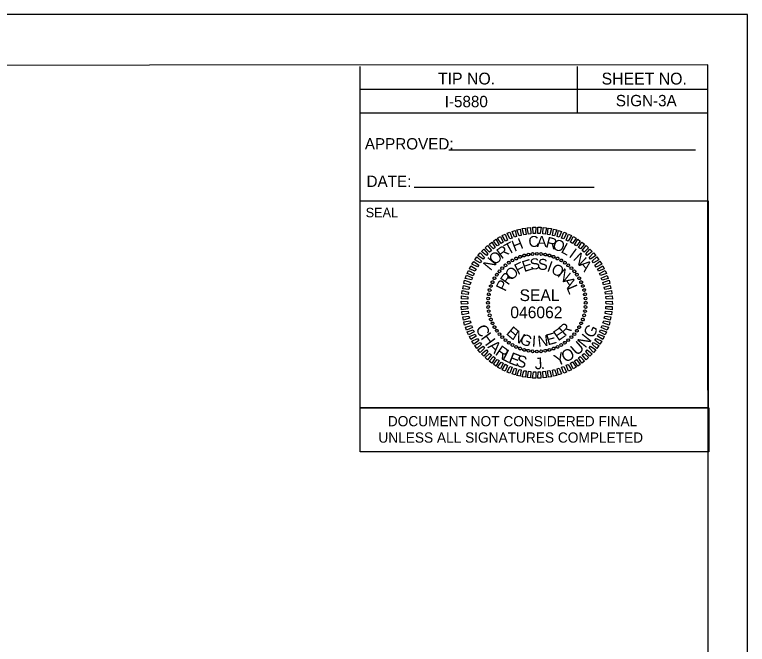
# Model space of a CAD drawing. Extents: x 1727387 to 1728895, y 539219 to 540208.
# Drawn here: x 1727645.2 to 1727723.8, y 539521.4 to 539589 of the extents above; entities that cross this region are included whole.
import ezdxf

# ---------------------------------------------------------------- set-up
doc = ezdxf.new("R2010")
doc.units = 0
for name, color, linetype in [('Default', 7, 'Continuous'), ('Old_Level_2', 7, 'Continuous'), ('Overhead Sheet Border', 7, 'Continuous'), ('Overhead Sheet Text', 7, 'Continuous'), ('Sheet Plot Border Outside CELL', 7, 'Continuous'), ('Sheet Sticker Exception Certification CELL', 7, 'Continuous')]:
    doc.layers.add(name, color=color, linetype=linetype)

msp = doc.modelspace()

# ---------------------------------------------------------------- linework, layer by layer
at = {"layer": 'Old_Level_2'}
for p, q in [((1727700.313, 539563.242), (1727700.313, 539563.242)), ((1727700.762, 539563.312), (1727700.762, 539563.312)), ((1727701.222, 539563.331), (1727701.222, 539563.331)), ((1727701.682, 539563.307), (1727701.682, 539563.307)), ((1727702.133, 539563.242), (1727702.133, 539563.242)), ((1727698.205, 539562.379), (1727698.205, 539562.379)), ((1727698.598, 539562.626), (1727698.598, 539562.626)), ((1727699.002, 539562.842), (1727699.002, 539562.842)), ((1727699.418, 539563.017), (1727699.418, 539563.017)), ((1727699.855, 539563.15), (1727699.855, 539563.15)), ((1727702.574, 539563.156), (1727702.574, 539563.156)), ((1727703.016, 539563.017), (1727703.016, 539563.017)), ((1727703.437, 539562.836), (1727703.437, 539562.836)), ((1727703.848, 539562.634), (1727703.848, 539562.634)), ((1727704.229, 539562.379), (1727704.229, 539562.379)), ((1727697.504, 539561.791), (1727697.504, 539561.791)), ((1727697.844, 539562.111), (1727697.844, 539562.111)), ((1727704.6, 539562.103), (1727704.6, 539562.103)), ((1727704.93, 539561.795), (1727704.93, 539561.795)), ((1727696.92, 539561.091), (1727696.92, 539561.091)), ((1727697.196, 539561.462), (1727697.196, 539561.462)), ((1727705.25, 539561.456), (1727705.25, 539561.456)), ((1727705.517, 539561.094), (1727705.517, 539561.094)), ((1727696.464, 539560.298), (1727696.464, 539560.298)), ((1727696.666, 539560.71), (1727696.666, 539560.71)), ((1727705.765, 539560.701), (1727705.765, 539560.701)), ((1727705.981, 539560.297), (1727705.981, 539560.297)), ((1727696.144, 539559.435), (1727696.144, 539559.435)), ((1727696.283, 539559.877), (1727696.283, 539559.877)), ((1727706.156, 539559.882), (1727706.156, 539559.882)), ((1727706.289, 539559.445), (1727706.289, 539559.445)), ((1727695.992, 539558.544), (1727695.992, 539558.544)), ((1727696.057, 539558.994), (1727696.057, 539558.994)), ((1727706.38, 539558.986), (1727706.38, 539558.986)), ((1727706.451, 539558.538), (1727706.451, 539558.538)), ((1727695.969, 539558.083), (1727695.969, 539558.083)), ((1727701.219, 539558.08), (1727701.219, 539558.08)), ((1727706.469, 539558.078), (1727706.469, 539558.078)), ((1727695.987, 539557.623), (1727695.987, 539557.623)), ((1727696.058, 539557.175), (1727696.058, 539557.175)), ((1727706.381, 539557.166), (1727706.381, 539557.166)), ((1727706.446, 539557.617), (1727706.446, 539557.617)), ((1727696.15, 539556.716), (1727696.15, 539556.716)), ((1727696.283, 539556.279), (1727696.283, 539556.279)), ((1727706.156, 539556.284), (1727706.156, 539556.284)), ((1727706.294, 539556.726), (1727706.294, 539556.726)), ((1727696.457, 539555.864), (1727696.457, 539555.864)), ((1727696.673, 539555.46), (1727696.673, 539555.46)), ((1727705.773, 539555.451), (1727705.773, 539555.451)), ((1727705.975, 539555.863), (1727705.975, 539555.863)), ((1727696.921, 539555.067), (1727696.921, 539555.067)), ((1727697.189, 539554.705), (1727697.189, 539554.705)), ((1727705.242, 539554.699), (1727705.242, 539554.699)), ((1727705.518, 539555.07), (1727705.518, 539555.07)), ((1727697.508, 539554.366), (1727697.508, 539554.366)), ((1727697.838, 539554.058), (1727697.838, 539554.058)), ((1727698.209, 539553.782), (1727698.209, 539553.782)), ((1727704.233, 539553.782), (1727704.233, 539553.782)), ((1727704.594, 539554.05), (1727704.594, 539554.05)), ((1727704.934, 539554.37), (1727704.934, 539554.37)), ((1727698.59, 539553.527), (1727698.59, 539553.527)), ((1727699.001, 539553.325), (1727699.001, 539553.325)), ((1727699.423, 539553.144), (1727699.423, 539553.144)), ((1727699.864, 539553.005), (1727699.864, 539553.005)), ((1727702.584, 539553.011), (1727702.584, 539553.011)), ((1727703.021, 539553.144), (1727703.021, 539553.144)), ((1727703.436, 539553.319), (1727703.436, 539553.319)), ((1727703.84, 539553.535), (1727703.84, 539553.535)), ((1727700.305, 539552.919), (1727700.305, 539552.919)), ((1727700.756, 539552.853), (1727700.756, 539552.853)), ((1727701.217, 539552.83), (1727701.217, 539552.83)), ((1727701.677, 539552.849), (1727701.677, 539552.849)), ((1727702.125, 539552.919), (1727702.125, 539552.919))]:
    msp.add_line(p, q, dxfattribs=at)
for points in [[(1727698.307, 539564.932), (1727698.025, 539565.534), (1727698.336, 539565.665), (1727698.567, 539565)], [(1727698.816, 539565.109), (1727698.565, 539565.732), (1727698.887, 539565.832), (1727699.035, 539565.186)], [(1727699.316, 539565.253), (1727699.085, 539565.908), (1727699.439, 539565.988), (1727699.535, 539565.309)], [(1727699.816, 539565.377), (1727699.637, 539566.043), (1727699.981, 539566.081), (1727700.066, 539565.413)], [(1727700.317, 539565.449), (1727700.19, 539566.116), (1727700.545, 539566.164), (1727700.567, 539565.484)], [(1727700.838, 539565.51), (1727700.774, 539566.189), (1727701.12, 539566.184), (1727701.09, 539565.504)], [(1727701.34, 539565.508), (1727701.329, 539566.188), (1727701.674, 539566.183), (1727701.592, 539565.502)], [(1727701.864, 539565.486), (1727701.894, 539566.166), (1727702.24, 539566.11), (1727702.115, 539565.449)], [(1727702.367, 539565.411), (1727702.45, 539566.082), (1727702.795, 539566.036), (1727702.619, 539565.384)], [(1727702.902, 539565.305), (1727702.995, 539565.987), (1727703.352, 539565.909), (1727703.123, 539565.257)], [(1727703.407, 539565.178), (1727703.552, 539565.829), (1727703.878, 539565.73), (1727703.627, 539565.109)], [(1727703.88, 539564.998), (1727704.109, 539565.661), (1727704.404, 539565.541), (1727704.122, 539564.929)], [(1727696.95, 539564.177), (1727696.554, 539564.703), (1727696.822, 539564.906), (1727697.178, 539564.306)], [(1727697.406, 539564.446), (1727697.009, 539565.004), (1727697.33, 539565.177), (1727697.602, 539564.575)], [(1727697.851, 539564.705), (1727697.506, 539565.284), (1727697.828, 539565.436), (1727698.079, 539564.803)], [(1727704.354, 539564.808), (1727704.605, 539565.429), (1727704.932, 539565.289), (1727704.586, 539564.697)], [(1727704.84, 539564.576), (1727705.111, 539565.177), (1727705.428, 539565.004), (1727705.04, 539564.454)], [(1727705.252, 539564.301), (1727705.608, 539564.913), (1727705.883, 539564.699), (1727705.484, 539564.179)], [(1727696.146, 539563.525), (1727695.678, 539563.977), (1727695.924, 539564.232), (1727696.342, 539563.674)], [(1727696.558, 539563.856), (1727696.1, 539564.35), (1727696.378, 539564.574), (1727696.755, 539563.995)], [(1727705.686, 539563.994), (1727706.063, 539564.576), (1727706.339, 539564.351), (1727705.888, 539563.851)], [(1727706.089, 539563.677), (1727706.509, 539564.228), (1727706.764, 539563.982), (1727706.291, 539563.524)], [(1727695.448, 539562.749), (1727694.897, 539563.147), (1727695.123, 539563.423), (1727695.591, 539562.94)], [(1727695.807, 539563.153), (1727695.266, 539563.572), (1727695.524, 539563.817), (1727695.971, 539563.323)], [(1727706.472, 539563.318), (1727706.913, 539563.817), (1727707.168, 539563.571), (1727706.632, 539563.153)], [(1727706.845, 539562.948), (1727707.317, 539563.427), (1727707.542, 539563.148), (1727706.995, 539562.741)], [(1727694.835, 539561.922), (1727694.244, 539562.226), (1727694.448, 539562.522), (1727694.999, 539562.114)], [(1727695.141, 539562.346), (1727694.571, 539562.692), (1727694.764, 539562.998), (1727695.274, 539562.547)], [(1727707.165, 539562.546), (1727707.67, 539562.994), (1727707.874, 539562.694), (1727707.294, 539562.349)], [(1727707.445, 539562.122), (1727707.992, 539562.529), (1727708.196, 539562.218), (1727707.595, 539561.915)], [(1727694.592, 539561.468), (1727693.991, 539561.719), (1727694.143, 539562.046), (1727694.714, 539561.669)], [(1727707.725, 539561.666), (1727708.304, 539562.042), (1727708.445, 539561.721), (1727707.854, 539561.47)], [(1727694.19, 539560.52), (1727693.539, 539560.697), (1727693.669, 539561.024), (1727694.301, 539560.742)], [(1727694.391, 539560.984), (1727693.739, 539561.213), (1727693.89, 539561.54), (1727694.492, 539561.216)], [(1727707.942, 539561.22), (1727708.553, 539561.545), (1727708.695, 539561.213), (1727708.05, 539560.992)], [(1727708.138, 539560.732), (1727708.771, 539561.015), (1727708.892, 539560.693), (1727708.247, 539560.514)], [(1727694.042, 539560.016), (1727693.391, 539560.14), (1727693.459, 539560.486), (1727694.122, 539560.237)], [(1727708.314, 539560.233), (1727708.979, 539560.485), (1727709.048, 539560.141), (1727708.391, 539560.015)], [(1727693.841, 539558.977), (1727693.17, 539559.028), (1727693.206, 539559.384), (1727693.888, 539559.228)], [(1727693.915, 539559.511), (1727693.265, 539559.584), (1727693.332, 539559.94), (1727693.995, 539559.732)], [(1727708.449, 539559.734), (1727709.104, 539559.944), (1727709.173, 539559.589), (1727708.515, 539559.515)], [(1727708.551, 539559.233), (1727709.229, 539559.392), (1727709.266, 539559.037), (1727708.598, 539558.983)], [(1727693.797, 539558.474), (1727693.117, 539558.483), (1727693.132, 539558.828), (1727693.814, 539558.725)], [(1727708.623, 539558.733), (1727709.301, 539558.828), (1727709.328, 539558.473), (1727708.648, 539558.482)], [(1727693.796, 539557.951), (1727693.117, 539557.908), (1727693.11, 539558.263), (1727693.791, 539558.202)], [(1727693.815, 539557.428), (1727693.137, 539557.333), (1727693.11, 539557.688), (1727693.79, 539557.679)], [(1727708.641, 539557.687), (1727709.321, 539557.678), (1727709.306, 539557.333), (1727708.625, 539557.436)], [(1727708.643, 539558.21), (1727709.322, 539558.253), (1727709.328, 539557.898), (1727708.647, 539557.959)], [(1727693.887, 539556.928), (1727693.21, 539556.769), (1727693.172, 539557.124), (1727693.841, 539557.178)], [(1727708.598, 539557.184), (1727709.268, 539557.133), (1727709.232, 539556.777), (1727708.55, 539556.932)], [(1727693.99, 539556.427), (1727693.334, 539556.217), (1727693.265, 539556.572), (1727693.923, 539556.646)], [(1727694.124, 539555.928), (1727693.459, 539555.675), (1727693.39, 539556.019), (1727694.047, 539556.146)], [(1727708.396, 539556.145), (1727709.047, 539556.021), (1727708.98, 539555.674), (1727708.316, 539555.924)], [(1727708.523, 539556.65), (1727709.173, 539556.577), (1727709.106, 539556.22), (1727708.444, 539556.429)], [(1727694.3, 539555.429), (1727693.667, 539555.146), (1727693.546, 539555.468), (1727694.192, 539555.646)], [(1727708.248, 539555.641), (1727708.9, 539555.464), (1727708.769, 539555.137), (1727708.137, 539555.419)], [(1727694.497, 539554.941), (1727693.885, 539554.616), (1727693.744, 539554.948), (1727694.388, 539555.169)], [(1727694.714, 539554.495), (1727694.135, 539554.118), (1727693.993, 539554.44), (1727694.585, 539554.691)], [(1727707.846, 539554.692), (1727708.447, 539554.441), (1727708.296, 539554.115), (1727707.724, 539554.492)], [(1727708.047, 539555.177), (1727708.699, 539554.948), (1727708.548, 539554.621), (1727707.947, 539554.945)], [(1727694.993, 539554.039), (1727694.446, 539553.632), (1727694.242, 539553.943), (1727694.843, 539554.246)], [(1727695.273, 539553.615), (1727694.768, 539553.167), (1727694.564, 539553.467), (1727695.144, 539553.812)], [(1727707.297, 539553.815), (1727707.868, 539553.469), (1727707.674, 539553.162), (1727707.164, 539553.614)], [(1727707.603, 539554.238), (1727708.194, 539553.935), (1727707.99, 539553.639), (1727707.439, 539554.047)], [(1727695.594, 539553.213), (1727695.121, 539552.734), (1727694.896, 539553.013), (1727695.444, 539553.42)], [(1727695.966, 539552.843), (1727695.525, 539552.344), (1727695.27, 539552.59), (1727695.806, 539553.008)], [(1727706.631, 539553.008), (1727707.172, 539552.589), (1727706.915, 539552.344), (1727706.467, 539552.838)], [(1727706.99, 539553.412), (1727707.541, 539553.014), (1727707.316, 539552.738), (1727706.847, 539553.221)], [(1727696.349, 539552.484), (1727695.93, 539551.933), (1727695.674, 539552.179), (1727696.148, 539552.637)], [(1727696.752, 539552.166), (1727696.375, 539551.585), (1727696.099, 539551.81), (1727696.551, 539552.309)], [(1727705.88, 539552.305), (1727706.338, 539551.811), (1727706.06, 539551.586), (1727705.684, 539552.166)], [(1727706.293, 539552.636), (1727706.761, 539552.184), (1727706.514, 539551.929), (1727706.096, 539552.486)], [(1727697.186, 539551.86), (1727696.831, 539551.248), (1727696.555, 539551.462), (1727696.954, 539551.982)], [(1727697.599, 539551.585), (1727697.327, 539550.984), (1727697.01, 539551.156), (1727697.398, 539551.707)], [(1727698.084, 539551.353), (1727697.833, 539550.732), (1727697.507, 539550.872), (1727697.852, 539551.464)], [(1727704.587, 539551.456), (1727704.932, 539550.876), (1727704.611, 539550.724), (1727704.359, 539551.358)], [(1727705.033, 539551.715), (1727705.429, 539551.157), (1727705.108, 539550.984), (1727704.836, 539551.586)], [(1727705.488, 539551.984), (1727705.884, 539551.458), (1727705.616, 539551.254), (1727705.26, 539551.855)], [(1727698.558, 539551.163), (1727698.329, 539550.5), (1727698.034, 539550.62), (1727698.316, 539551.232)], [(1727699.032, 539550.983), (1727698.886, 539550.332), (1727698.56, 539550.431), (1727698.811, 539551.052)], [(1727699.536, 539550.855), (1727699.443, 539550.174), (1727699.086, 539550.251), (1727699.315, 539550.904)], [(1727700.071, 539550.75), (1727699.989, 539550.079), (1727699.643, 539550.125), (1727699.82, 539550.777)], [(1727700.574, 539550.675), (1727700.544, 539549.995), (1727700.198, 539550.051), (1727700.323, 539550.712)], [(1727701.098, 539550.653), (1727701.11, 539549.973), (1727700.764, 539549.977), (1727700.847, 539550.659)], [(1727701.6, 539550.651), (1727701.664, 539549.972), (1727701.319, 539549.977), (1727701.349, 539550.657)], [(1727702.122, 539550.712), (1727702.248, 539550.045), (1727701.894, 539549.997), (1727701.871, 539550.677)], [(1727702.622, 539550.784), (1727702.801, 539550.118), (1727702.457, 539550.08), (1727702.372, 539550.748)], [(1727703.122, 539550.908), (1727703.353, 539550.253), (1727702.999, 539550.173), (1727702.904, 539550.851)], [(1727703.622, 539551.052), (1727703.873, 539550.429), (1727703.551, 539550.329), (1727703.404, 539550.975)], [(1727704.131, 539551.229), (1727704.414, 539550.627), (1727704.102, 539550.496), (1727703.871, 539551.161)]]:
    msp.add_lwpolyline(points, close=True, dxfattribs=at)
for centre, major_axis in [((1727699.425, 539563.009), (-0.052, 0.142)), ((1727699.862, 539563.147), (-0.039, 0.145)), ((1727700.308, 539563.246), (-0.026, 0.148)), ((1727700.762, 539563.306), (-0.013, 0.15)), ((1727701.219, 539563.326), (0, 0.151)), ((1727701.676, 539563.306), (0.013, 0.15)), ((1727702.13, 539563.246), (0.026, 0.148)), ((1727702.577, 539563.147), (0.039, 0.145)), ((1727703.013, 539563.009), (0.052, 0.142)), ((1727698.211, 539562.377), (-0.086, 0.123)), ((1727698.596, 539562.623), (-0.075, 0.13)), ((1727699.002, 539562.834), (-0.064, 0.136)), ((1727703.436, 539562.834), (0.064, 0.136)), ((1727703.842, 539562.623), (0.075, 0.13)), ((1727704.228, 539562.377), (0.086, 0.123)), ((1727697.201, 539561.452), (-0.115, 0.097)), ((1727697.51, 539561.789), (-0.106, 0.106)), ((1727697.848, 539562.099), (-0.097, 0.115)), ((1727704.591, 539562.099), (0.097, 0.115)), ((1727704.928, 539561.789), (0.106, 0.106)), ((1727705.237, 539561.452), (0.115, 0.097)), ((1727696.677, 539560.703), (-0.13, 0.075)), ((1727696.922, 539561.089), (-0.123, 0.086)), ((1727705.516, 539561.089), (0.123, 0.086)), ((1727705.762, 539560.703), (0.13, 0.075)), ((1727696.29, 539559.874), (-0.142, 0.052)), ((1727696.465, 539560.297), (-0.136, 0.064)), ((1727705.973, 539560.297), (0.136, 0.064)), ((1727706.148, 539559.874), (0.142, 0.052)), ((1727696.153, 539559.438), (-0.145, 0.039)), ((1727706.286, 539559.438), (0.145, 0.039)), ((1727695.994, 539558.538), (-0.15, 0.013)), ((1727696.054, 539558.991), (-0.148, 0.026)), ((1727706.385, 539558.991), (0.148, 0.026)), ((1727706.444, 539558.538), (0.15, 0.013)), ((1727695.974, 539558.08), (-0.151, 0)), ((1727695.994, 539557.623), (-0.15, -0.013)), ((1727706.444, 539557.623), (0.15, -0.013)), ((1727706.464, 539558.08), (0.151, 0)), ((1727696.054, 539557.17), (-0.148, -0.026)), ((1727696.153, 539556.723), (-0.145, -0.039)), ((1727706.286, 539556.723), (0.145, -0.039)), ((1727706.385, 539557.17), (0.148, -0.026)), ((1727696.29, 539556.286), (-0.142, -0.052)), ((1727706.148, 539556.286), (0.142, -0.052)), ((1727696.465, 539555.864), (-0.136, -0.064)), ((1727696.677, 539555.458), (-0.13, -0.075)), ((1727705.762, 539555.458), (0.13, -0.075)), ((1727705.973, 539555.864), (0.136, -0.064)), ((1727696.922, 539555.072), (-0.123, -0.086)), ((1727697.201, 539554.709), (-0.115, -0.097)), ((1727697.51, 539554.371), (-0.106, -0.106)), ((1727704.928, 539554.371), (0.106, -0.106)), ((1727705.237, 539554.709), (0.115, -0.097)), ((1727705.516, 539555.072), (0.123, -0.086)), ((1727697.848, 539554.062), (-0.097, -0.115)), ((1727698.211, 539553.784), (-0.086, -0.123)), ((1727704.228, 539553.784), (0.086, -0.123)), ((1727704.591, 539554.062), (0.097, -0.115)), ((1727698.596, 539553.538), (-0.075, -0.13)), ((1727699.002, 539553.327), (-0.064, -0.136)), ((1727699.425, 539553.151), (-0.052, -0.142)), ((1727699.862, 539553.014), (-0.039, -0.145)), ((1727700.308, 539552.915), (-0.026, -0.148)), ((1727700.762, 539552.855), (-0.013, -0.15)), ((1727701.219, 539552.835), (0, -0.151)), ((1727701.676, 539552.855), (0.013, -0.15)), ((1727702.13, 539552.915), (0.026, -0.148)), ((1727702.577, 539553.014), (0.039, -0.145)), ((1727703.013, 539553.151), (0.052, -0.142)), ((1727703.436, 539553.327), (0.064, -0.136)), ((1727703.842, 539553.538), (0.075, -0.13))]:
    msp.add_ellipse(centre, major_axis=major_axis, ratio=0.999708, dxfattribs=at)
at = {"layer": 'Overhead Sheet Border'}
for p, q in [((1727682.236, 539578.465), (1727682.236, 539583.449)), ((1727705.566, 539578.462), (1727705.566, 539583.451)), ((1727682.236, 539581.01), (1727705.566, 539581.007)), ((1727705.566, 539581.007), (1727719.601, 539581.006)), ((1727682.236, 539578.465), (1727719.601, 539578.461)), ((1727682.236, 539569.037), (1727682.236, 539578.465))]:
    msp.add_line(p, q, dxfattribs=at)
for points in [[(1727719.565, 539583.627), (1727419.828, 539583.466), (1727419.941, 539373.65), (1727719.678, 539373.811)], [(1727682.236, 539569.037), (1727719.601, 539569.037), (1727719.601, 539546.776), (1727682.236, 539546.776)]]:
    msp.add_lwpolyline(points, close=True, dxfattribs=at)
at = {"layer": 'Overhead Sheet Text'}
for p, q in [((1727691.766, 539574.484), (1727718.265, 539574.484)), ((1727688.032, 539570.506), (1727707.372, 539570.506))]:
    msp.add_line(p, q, dxfattribs=at)
at = {"layer": 'Sheet Plot Border Outside CELL'}
msp.add_lwpolyline([(1727723.818, 539589.019), (1727387.253, 539589.019), (1727387.253, 539369.849), (1727723.818, 539369.849)], close=True, dxfattribs=at)
at = {"layer": 'Sheet Sticker Exception Certification CELL'}
for p, q in [((1727705.566, 539578.462), (1727705.566, 539583.451)), ((1727719.601, 539583.449), (1727719.601, 539583.449)), ((1727719.601, 539583.449), (1727719.601, 539583.449)), ((1727719.601, 539583.449), (1727719.601, 539583.449)), ((1727719.601, 539583.449), (1727719.601, 539583.449)), ((1727719.601, 539583.449), (1727719.601, 539583.449)), ((1727719.601, 539583.449), (1727719.601, 539583.449)), ((1727719.601, 539583.449), (1727719.601, 539583.449)), ((1727719.601, 539583.449), (1727719.601, 539583.449))]:
    msp.add_line(p, q, dxfattribs=at)
msp.add_lwpolyline([(1727682.236, 539546.776), (1727719.693, 539546.776), (1727719.693, 539542.081), (1727682.236, 539542.081)], close=True, dxfattribs=at)

# ---------------------------------------------------------------- texts
at = {"layer": 'Default'}
for s, rotation, p in [('C', 297.19982, (1727694.596, 539555.334)), ('G', 61.79975, (1727707.241, 539554.181)), ('H', 306.64359, (1727695.135, 539554.285)), ('N', 51.22881, (1727706.424, 539553.143)), ('A', 316.48339, (1727695.873, 539553.3)), ('U', 41.43471, (1727705.509, 539552.33)), ('R', 325.19604, (1727696.658, 539552.545)), ('L', 332.56827, (1727697.406, 539552.006)), ('O', 30.04125, (1727704.289, 539551.596)), ('E', 338.75242, (1727698.082, 539551.63)), ('S', 345.75909, (1727698.892, 539551.295)), ('J', 3.03206, (1727701.011, 539550.91)), ('Y', 22.24252, (1727703.381, 539551.24)), ('.', 8.21395, (1727701.659, 539550.92))]:
    msp.add_text(s, height=1.254, rotation=rotation, dxfattribs=at).set_placement(p)
at = {"layer": 'Old_Level_2'}
for s, height, rotation, p in [('H', 1.179, 21.61945, (1727698.812, 539563.55)), ('C', 1.179, 7.21984, (1727700.394, 539563.996)), ('A', 1.179, 0.02029, (1727701.219, 539564.073)), ('R', 1.179, 345.62106, (1727702.098, 539564.047)), ('O', 1.179, 338.42113, (1727702.801, 539563.902)), ('R', 1.179, 36.02047, (1727697.436, 539562.721)), ('T', 1.179, 28.81974, (1727698.139, 539563.193)), ('L', 1.179, 331.22084, (1727703.728, 539563.531)), ('O', 1.179, 43.22171, (1727696.726, 539562.06)), ('I', 1.179, 324.02011, (1727704.584, 539563.044)), ('N', 1.179, 316.81888, (1727705.039, 539562.728)), ('N', 1.179, 50.42347, (1727696.255, 539561.445)), ('F', 1.179, 26.967, (1727699.191, 539561.036)), ('E', 1.179, 17.61103, (1727699.855, 539561.362)), ('S', 1.179, 8.25558, (1727700.572, 539561.594)), ('S', 1.179, 358.90037, (1727701.325, 539561.617)), ('I', 1.179, 340.18957, (1727702.226, 539561.487)), ('A', 1.179, 309.61712, (1727705.667, 539562.122)), ('O', 1.179, 45.68121, (1727698.512, 539560.407)), ('O', 1.179, 330.83345, (1727702.647, 539561.348)), ('N', 1.179, 321.47658, (1727703.355, 539560.942)), ('R', 1.179, 55.03962, (1727698.155, 539559.889)), ('P', 1.179, 64.39886, (1727697.832, 539559.214)), ('A', 1.179, 302.76023, (1727703.961, 539560.408)), ('L', 1.179, 293.40082, (1727704.381, 539559.694)), ('SEAL', 1.2545, 359.99997, (1727699.365, 539558.257)), ('046062', 1.2549, 359.99997, (1727698.37, 539556.417)), ('E', 1.179, 319.27686, (1727697.847, 539554.748)), ('E', 1.179, 34.12406, (1727703.499, 539553.916)), ('R', 1.179, 43.48138, (1727704.232, 539554.42)), ('N', 1.179, 328.63392, (1727698.484, 539554.194)), ('G', 1.179, 337.99021, (1727699.287, 539553.738)), ('I', 1.179, 356.70117, (1727700.663, 539553.364)), ('N', 1.179, 6.05636, (1727701.365, 539553.345)), ('E', 1.179, 15.41173, (1727702.397, 539553.489))]:
    msp.add_text(s, height=height, rotation=rotation, dxfattribs=at).set_placement(p)
at = {"layer": 'Overhead Sheet Text'}
for s, height, p in [('TIP NO.', 1.2704, (1727690.602, 539581.518)), ('SHEET NO.', 1.2704, (1727708.169, 539581.516)), ('I-5880', 1.2208, (1727691.328, 539579.076)), ('SIGN-3A', 1.2208, (1727709.701, 539579.178)), ('APPROVED:', 1.2208, (1727682.753, 539574.537)), ('DATE:', 1.2208, (1727682.937, 539570.512)), ('SEAL', 1.018, (1727682.841, 539567.257))]:
    msp.add_text(s, height=height, rotation=359.99494, dxfattribs=at).set_placement(p)
at = {"layer": 'Sheet Sticker Exception Certification CELL'}
for s, p in [('DOCUMENT NOT CONSIDERED FINAL', (1727685.218, 539544.807)), ('UNLESS ALL SIGNATURES COMPLETED', (1727684.205, 539543.049))]:
    msp.add_text(s, height=1.09894, dxfattribs=at).set_placement(p)

doc.saveas('drawing.dxf')
